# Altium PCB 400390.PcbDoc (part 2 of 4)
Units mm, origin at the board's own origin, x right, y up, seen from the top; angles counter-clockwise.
Board outline 50.8 x 50.4 mm, 4 copper layers (Top Layer, Mid Layer 1, Mid Layer 2, Bottom Layer), stack 1.507 mm thick; 236 components, 197 nets, 1131 pads, 994 vias.
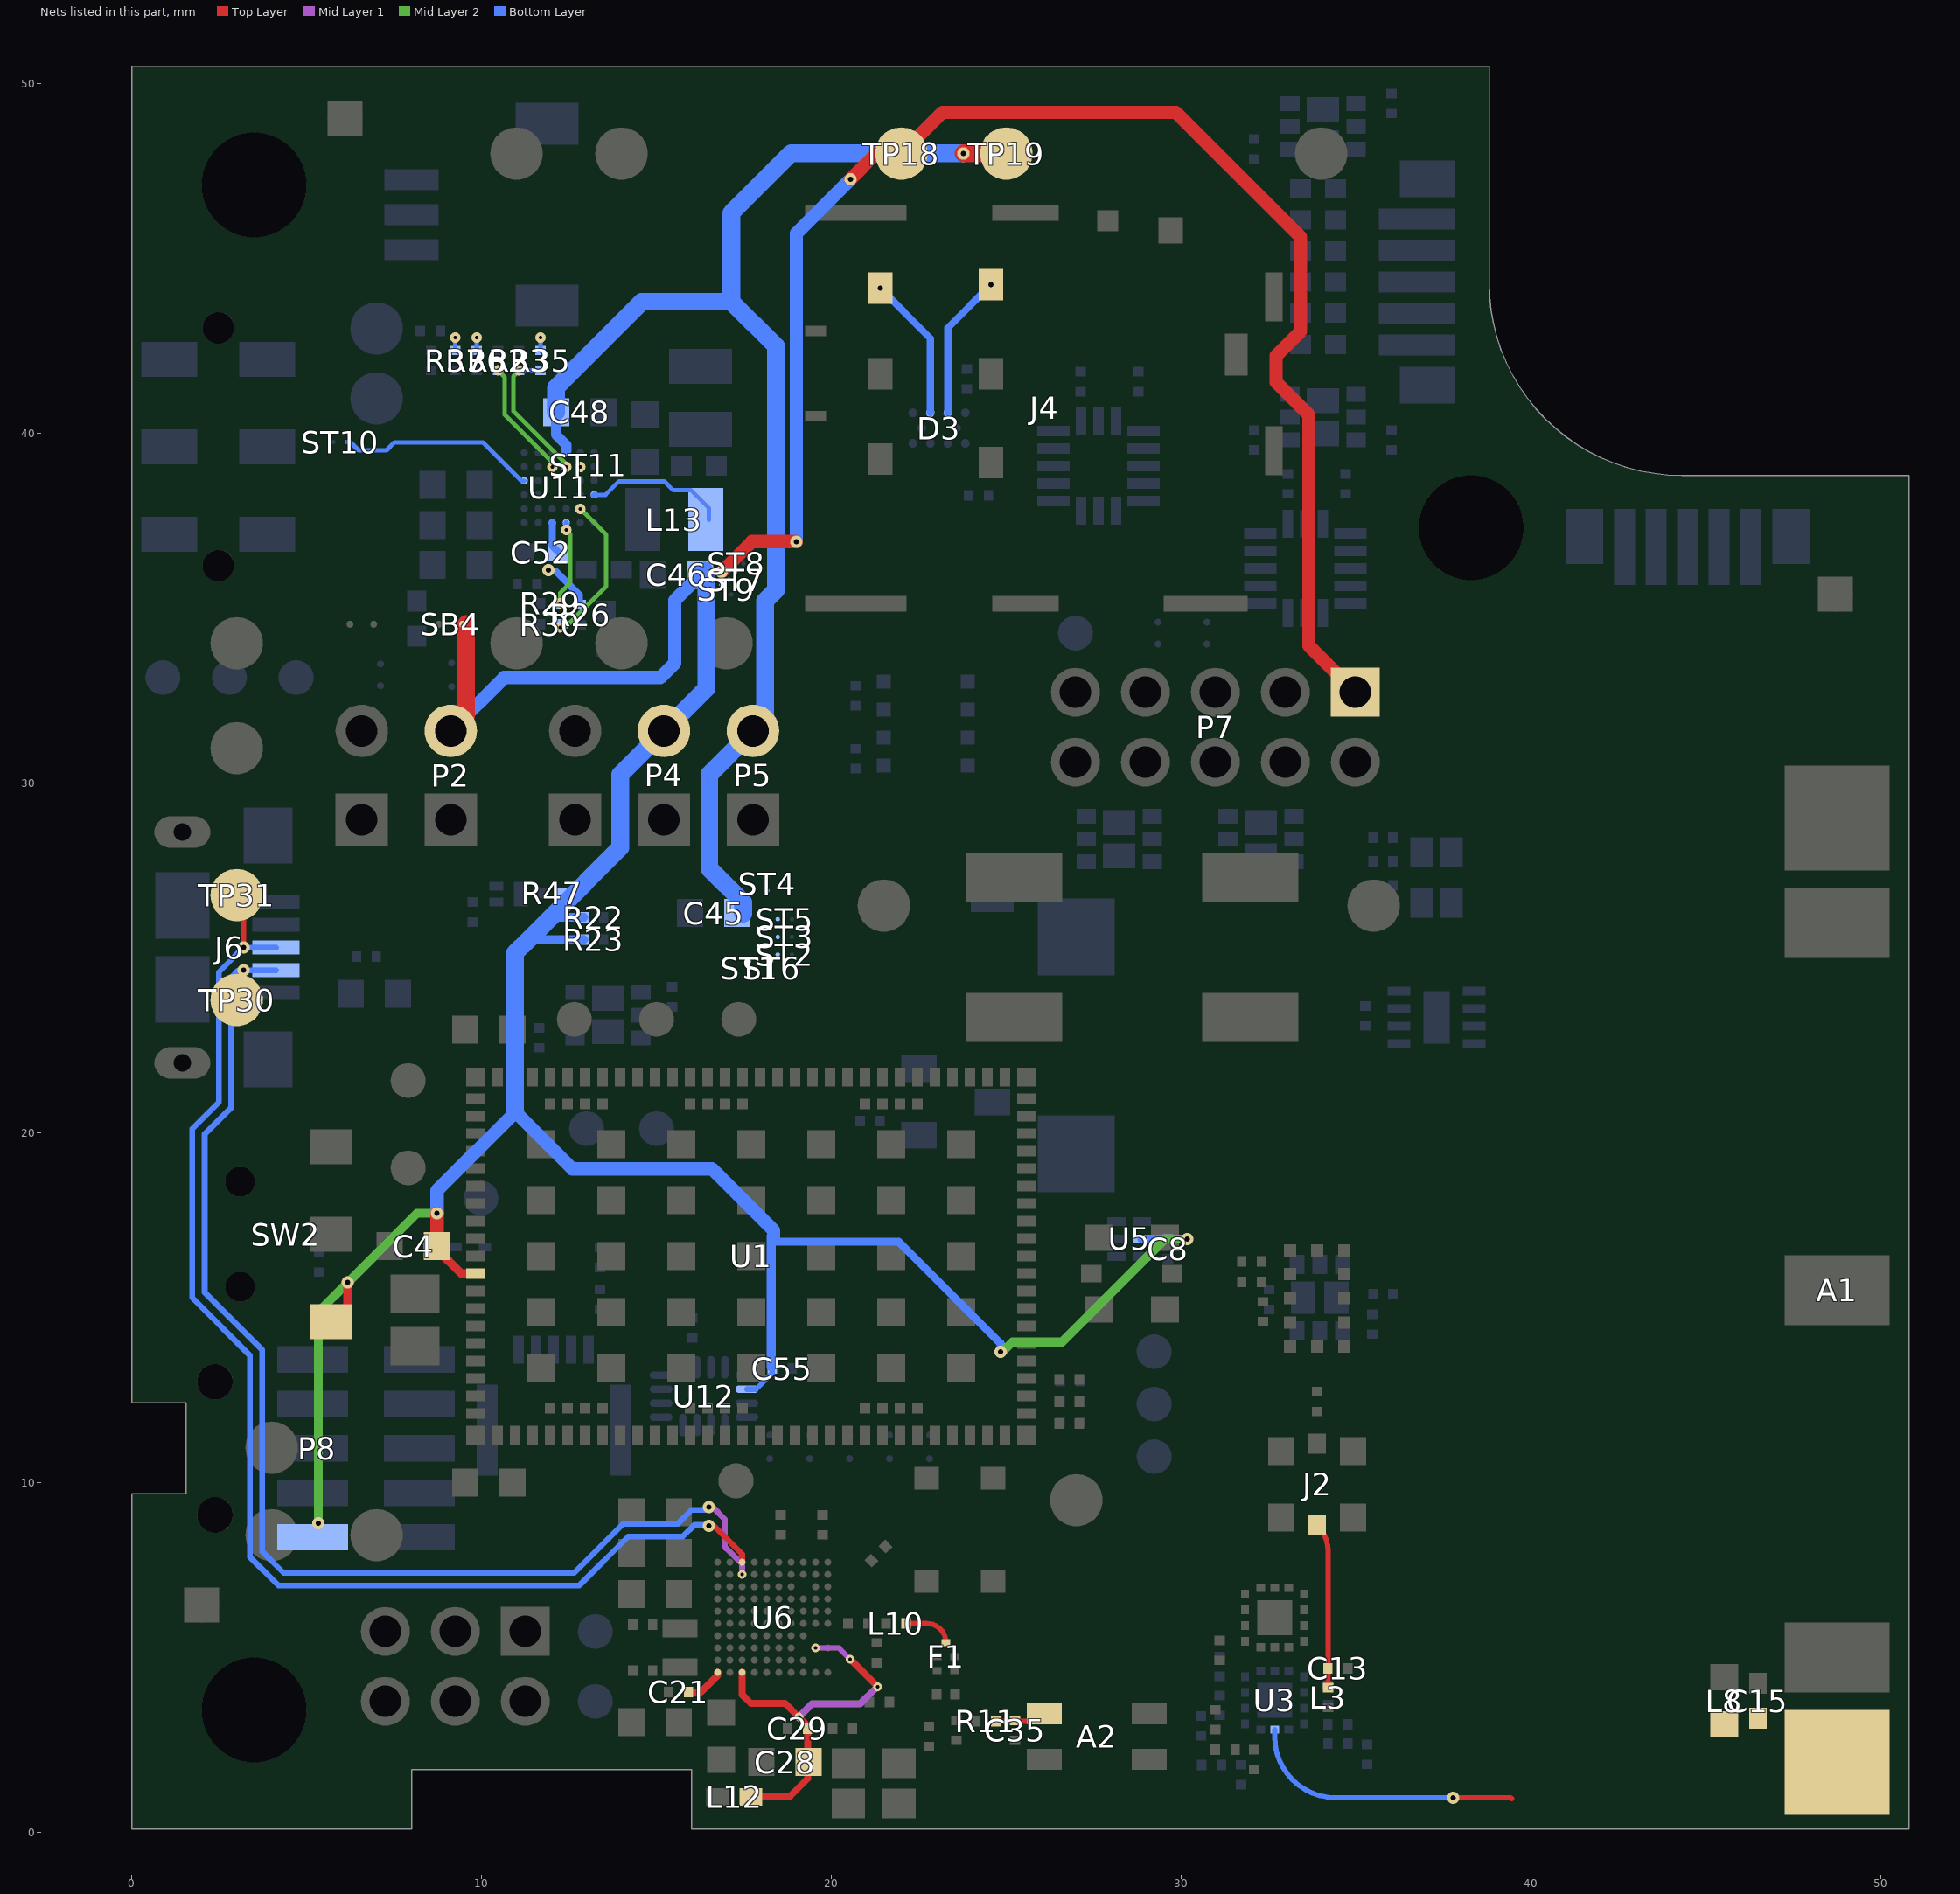
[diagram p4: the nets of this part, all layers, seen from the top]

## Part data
A1: library part FR01-S4-210-D, "Mobile IoT LTE Multi-Band Antenna", Manufacturer="Fractus Antennas", Part number IPS=80000001819
A2: library part "Johanson 2450AT18D0100_STD-R", "2.45 GHz chip antenna", Manufacturer="Johanson Technology", Part number IPS=00000001415, Supplier Part Number 1=2450AT18D0100E
Bz1: library part AST7525MATRQ, "Buzzer Transducer, 3.6V 100mA 2.7kHz 85dB @ 3.6V, SMD", Manufacturer=Mallory, Part number IPS=00000001770, Supplier Part Number 1=458-1100-1-ND
C1 C2 C4 C45 C50: library part C0603-4µ7, "Capacitor, X5R, ±10%", Part number IPS=00000007783
C3: library part C0805-47µ, "Capacitor, X5R, ±20%, 6.3V", Manufacturer="Taiyo Yuden", Manufacturer Part Number=JMK212BJ476MG-T, Part number IPS=N.A., Supplier Part Number 1=587-1779-2-ND
C5: library part C0201-100p, "Capacitor, NP0, ±2%, 25V", Part number IPS=00000007853
C6 C8 C21 C23 C24 C26 C36 C37 C38 C39 C40 C41 C42 C44 C55: library part C0201-100n, "Capacitor, X5R, ±10%", Part number IPS=00000001248
C7: library part C0201-6.8p, "Capacitor, NP0, ±0.25pF, 25V", Part number IPS=00000005766
C9: library part C0201-2.5p-HQ-Murata, "Capacitor, NP0, ±0.05pF, 25V", Manufacturer=Murata, Manufacturer Part Number=GJM0333C1E2R5WB01, Part number IPS=00000001771
C10: library part C0201-5.5p-HQ-Murata, "Capacitor, NP0, ±0.05pF, 25V", Manufacturer=Murata, Manufacturer Part Number=GJM0332C1H5R5WB01, Part number IPS=00000001772
C11: library part C0201-9.2p-HQ-Murata, "Capacitor, NP0, ±0.05pF, 25V", Manufacturer=Murata, Manufacturer Part Number=GJM0332C1E9R2WB01, Part number IPS=N.A.
C12: library part C0201-1.5p-HQ-Murata, "Capacitor, NP0, ±0.05pF, 25V", Manufacturer=Murata, Manufacturer Part Number=GJM0334C1E1R5WB01, Part number IPS=00000001774
C13: library part C0201-3.9p-HQ-Murata, "Capacitor, NP0, ±0.05pF, 25V", Manufacturer=Murata, Manufacturer Part Number=GJM0333C1E3R9WB01, Part number IPS=N.A.
C14: library part C0201-3.1p-HQ-Murata, "Capacitor, NP0, ±0.05pF, 25V", Manufacturer=Murata, Manufacturer Part Number=GJM0335C1E3R1WB01, Part number IPS=00000001776
C15: library part C0402-0.3p-HQ-Murata, "Capacitor, NP0, ±0.05pF, 50V", Manufacturer=Murata, Manufacturer Part Number=GJM1555C1HR30WB01D, Part number IPS=00000001777, Supplier Part Number 1=490-11248-1-ND
C16 C17: library part C0201-2n2, "Capacitor, X7R, ±10%, 10V", Part number IPS=00000001778
C18 C19 C30 C31: library part C0201-12p, "Capacitor, NP0, ±2%", Part number IPS=00000007848
C20: library part C0201-1.0p, "Capacitor, NP0, ±0.05pF, 50V", Part number IPS=00000001247
C22 C32: library part C0603-4µ7-6.3V-X7R, "Capacitor, X7R, ±10%, 6.3V", Manufacturer=Samsung, Manufacturer Part Number=CL10B475KQ8NQNC, Part number IPS=00000002541, Supplier Part Number 1=1276-2087-1-ND
C25: library part C0201-820p, "Capacitor, X7R, ±10%", Part number IPS=00000001249
C27 C28 C49: library part C0603-1µ0, "Capacitor, X7R, ±10%", Part number IPS=00000000616
C29: library part C0201-47n, "Capacitor, X5R, ±10%", Part number IPS=00000001250
C33: library part C0603-4µ7-10V-X7S, "Capacitor, X7S, ±10%, 10V", Part number IPS=00000001779, Supplier Part Number 1=445-14258-1-ND
C35: library part C0201-0.8p, "Capacitor, NP0, ±0.05pF, 50V", Manufacturer=Murata, Manufacturer Part Number=GJM0335C1HR80WB01, Part number IPS=N.A.
C43 C51: library part C0603-10µ, "Capacitor, X5R, ±20%", Part number IPS=00000007785
C46 C48: library part C0603-22µ-6.3V, "CAP CER 22UF 6.3V 20% X5R 0603", Manufacturer=Samsung, Manufacturer Part Number=CL10A226MQ8NRNC, Part number IPS=00000007787, Supplier Part Number 1=1276-1193-1-ND
C47 C52: library part C0402-1µ0, "Capacitor, X5R, ±5%", Part number IPS=00000007786, Supplier Part Number 1=1276-1444-1-ND
C53: library part C0603-2µ2-10V, "Capacitor, X7R, ±10%, 10V", Manufacturer=Samsung, Manufacturer Part Number=CL10B225KP8NNNC, Part number IPS=00000001781, Supplier Part Number 1=1276-1134-1-ND
C54: library part C0201-10n, "Capacitor, X7R, ±10%", Part number IPS=00000003480
C56 C57: library part C0201-560p, "Capacitor, NP0, ±5%, 25V", Part number IPS=N.A.
CR1: "TVS DIODE 4V 0201", Manufacturer=Murata, Part number IPS=00000001782, Supplier Part Number 1=490-14310-1-ND
D1: "20V schottky barrier diode, Vf 350 mV @ 100 mA, Ir 2.0 µA @ 10 V, If 500 mA", Manufacturer="ON Semiconductor", Part number IPS=00000009952, Supplier Part Number 1=NSR0620P2T5GOSCT-ND
D2: "1N4148, Small Signal Fast Switching Diode", Manufacturer=Vishay, Manufacturer Part Number=1N4148W-E3-08, Part number IPS=00000001783, Supplier Part Number 1=237-7282
D3: "EMI Network Filter Arrays SIM CARD EMI FILTER WITH ESD PROTECTION", Manufacturer="ON Semiconductor", Manufacturer Part Number=CM1402-03CP, Part number IPS=00000009949, Supplier Part Number 1=CM1402-03CPOSTR-ND
F1: "2.4 GHz BPF", Manufacturer=MuRata, Part number IPS=00000001784
Fid1 Fid2 Fid3: library part Fid-Mark-Round-Square, "Fiducial Mark", Part number IPS=N.A.
H1 H2 H3: library part Hole_3MM_NP, "Regular Non-Plated, 3mm hole", Manufacturer="Nordic Semiconductor", Part number IPS=N.A.
J1 J2: "Coaxial Connector with Switch", Manufacturer=Murata, Part number IPS=00000009955, Supplier Part Number 1=490-4981-1-ND
J3: library part SM03B-SRSS-TB, "1.0mm pitch connector side entry SMD", Manufacturer=JST, Manufacturer Part Number=SM03B-SRSS-TB(LF)(SN), Part number IPS=00000001785, Supplier Part Number 1=455-1803-1-ND
J4: "n 8 (6 + 2) Position Card Connector NANO SIM Surface Mount, Right Angle Gold", Manufacturer=JAE, Part number IPS=00000009956, Supplier Part Number 1=670-2799-1-ND
J5: library part FPC_05P-0.5mm-RA-SMD, "0.5mm FPC, 5P,Right Angle SMT,Double Contact,H=1.2mm,White, Tin plated", Manufacturer=W-CON, Manufacturer Part Number=5141-05RZDNWR01, Part number IPS=00000007792
J6: library part USB-Micro-B-RA-SMD-PiP, "MicroUSB-B-SMT", Manufacturer="Allen Creations Corp.", Manufacturer Part Number=AJU55-BS2111-L, Part number IPS=00000007790
L1: library part L0201-3n3-Wirewound-Murata, "Inductor, 520mA, ±0.2nH, 110mOhm, Q=47", Manufacturer=Murata, Manufacturer Part Number=LQW03AW3N3C00, Part number IPS=00000001786, Supplier Part Number 1=490-13831-1-ND
L2: library part L0201-5n6, "Inductor, 350mA, ±3%", Manufacturer=Murata, Manufacturer Part Number=LQP03TN5N6H02D, Part number IPS=00000001416
L3: library part L0201-2n9-Wirewound-Murata, "Inductor, 540mA, ±0.2nH, 100mOhm, Q=41", Manufacturer=Murata, Manufacturer Part Number=LQW03AW2N9C00, Part number IPS=00000001787, Supplier Part Number 1=490-13827-1-ND
L4: library part L0201-N.C., "Not mounted", Part number IPS=N.A.
L5: library part L0201-6n2-Wirewound-Murata, "Inductor, 360mA, ±5%, 220mOhm, Q=39", Manufacturer=Murata, Manufacturer Part Number=LQW03AW6N2J00, Part number IPS=N.A., Supplier Part Number 1=490-13840-1-ND
L6: library part L0201-5n1-Wirewound-Murata, "Inductor, 480mA, ±5%, 140mOhm, Q=45", Manufacturer=Murata, Manufacturer Part Number=LQW03AW5N1J00, Part number IPS=00000001789, Supplier Part Number 1=490-13839-1-ND
L7: library part L0201-4n7-Wirewound-Murata, "Inductor, 620mA, ±5%, 90mOhm, Q=45", Manufacturer=Murata, Manufacturer Part Number=LQW03AW4N7J00, Part number IPS=00000001790, Supplier Part Number 1=490-13838-1-ND
L8: library part L0603-15n-HQ-Murata, "Inductor, 1400mA, ±2%, 75mOhm", Manufacturer=Murata, Manufacturer Part Number=LQW18AN15NG80D, Part number IPS=00000001791, Supplier Part Number 1=490-18132-1-ND
L9: library part L0201-3n9, "Inductor, 400mA, ±0.1nH", Manufacturer=Murata, Manufacturer Part Number=LQP03TN3N9B02D, Part number IPS=00000001253
L10: library part L0201-4n7, "Inductor, 350mA, ±3%", Manufacturer=Murata, Manufacturer Part Number=LQP03TN4N7H02D, Part number IPS=00000001792
L11: library part L0603-10µ, "Inductor, 80mA, ±10%", Manufacturer="Taiyo Yuden", Manufacturer Part Number=LBMF1608T100K, Part number IPS=00000007794, Supplier Part Number 1=587-1714-1-ND
L12: library part L0402-15n, "Inductor, 320mA, ±5%", Manufacturer="Taiyo Yuden", Manufacturer Part Number=HK100515NJ-T, Part number IPS=00000001262, Supplier Part Number 1=587-1521-1-ND
L13 L14: library part L0806-2µ2-1.2A-110mOhm, "Shielded Multilayer Inductor, 1.2A, ±20%, 110mOhm, Q=10 @ 1MHz", Manufacturer="Wurth Electronics", Manufacturer Part Number=74479776222A, Part number IPS=80000001820, Supplier Part Number 1=732-2954-1-ND
L15: library part L0201-2n7-HQ-Murata, "Inductor, 600mA, ±0.1nH, 120mOhm", Manufacturer=Murata, Manufacturer Part Number=LQP03HQ2N7B02, Part number IPS=N.A., Supplier Part Number 1=490-13909-1-ND
LD1: library part LTST-C19HE1WT, "RGB LED 1.60 mm x 1.60 mm SMD", Manufacturer="Lite-On Inc", Part number IPS=00000007798, Supplier Part Number 1=160-2162-1-ND
LD2 LD3: library part MSL0104RGBU1, "High brightness, side view RGB LED", Manufacturer=ROHM, Part number IPS=00000007799, Supplier Part Number 1=MSL0104RGBU1CT-ND
P1 P2 P3 P4 P5: library part "Pin List 1x2, N.C.", "Pin List 1x2, 2.54mm (100mil)", Part number IPS=N.A.
P6: library part "Pin Header 2x3 TH, 2.00mm, N.C.", "Pin Header 2x3, TH, 2.00mm", Part number IPS=N.A.
P7: library part "Pin Header 2x5 TH, 2.00mm, N.C.", "Pin Header 2x5, TH, 2.00mm", Part number IPS=N.A.
P8: library part "Pin Header 2x5 SMD, 1.27mm, Angled", "Pin Header 2x5, 1.27mm (50mil)", Manufacturer=Samtec, Manufacturer Part Number=FTSH-105-01-L-DH-A-C-TR, Part number IPS=00000007800
Q1: "Dual N & P Ch MOFET, 11.6A/9A, 90mOhm max, 6.25W", Manufacturer="Taiwan Semiconductor", Part number IPS=00000001702, Supplier Part Number 1=TSM2537CQRFGCT-ND
Q2 Q3 Q4 Q6 Q7: "Dual N Ch MOFET, 5.8A, 55mOhm max, 620mW", Manufacturer="Taiwan Semiconductor", Part number IPS=00000001703, Supplier Part Number 1=TSM250N02DCQRFGCT-ND
Q5: "BC847C, NPN Silicon transistor", Manufacturer=NXP, Part number IPS=00000001793, Supplier Part Number 1=108-1235
Q8: "N-Channel MOSFET, 20V, 1A, 470mOhm, 400mW", Manufacturer="Rohm Semiconductor", Part number IPS=N.A., Supplier Part Number 1=RV2C010UNT2LCT-ND
R1 R2 R3 R21 R47: library part R0201-1k0, "Resistor, ±1%, 0.05W", Part number IPS=00000005786
R4 R5 R6 R8 R30 R32 R41 R42 R43 R44 R45 R46: library part R0201-1M0, "Resistor, ±1%, 0.05W", Part number IPS=00000001418
R7: library part R0201-3k0, "Resistor, ±1%, 0.05W", Part number IPS=00000001688
R9 R10 R11 R38: library part R0201-0R, "Resistor, ±5%, 0.05W", Part number IPS=00000003245
R12: library part R0201-100, "Resistor, ±1%, 0.05W", Part number IPS=00000001794
R13 R14: library part R0201-39R, "Resistor, ±1%, 0.05W", Part number IPS=00000001704
R15 R18: library part R0402-169, "Resistor, ±1%, 0.063W", Part number IPS=00000007805, Supplier Part Number 1=541-169LCT-ND
R16 R19: library part R0402-7R15, "Resistor, ±1%, 0.063W", Part number IPS=00000007806, Supplier Part Number 1=541-7.15LLCT-ND
R17 R20: library part R0402-11R, "Resistor, ±1%, 0.063W", Part number IPS=00000007807, Supplier Part Number 1=214-0577
R22 R23: library part R0201-4k7, "Resistor, ±1%, 0.05W", Part number IPS=00000001706
R24: library part R0402-0R1, "Resistor, ±1%, 0.063W", Part number IPS=00000001795, Supplier Part Number 1=311-.10PDKR-ND
R25 R31: library part R0402-2R2, "Resistor, ±1%, 0.063W", Part number IPS=00000001796
R26 R29 R33: library part R0201-N.C., "Not mounted", Part number IPS=N.A.
R27 R28 R34 R35 R36 R37: library part R0201-10k, "Resistor, ±1%, 0.05W", Part number IPS=00000001255
R39 R40: library part R0201-100k, "Resistor, ±1%, 0.05W", Part number IPS=00000001419
R48: library part R0201-10M, "Resistor, ±1%, 0.05W", Part number IPS=00000001426
SB1 SB3 SB4 SB7 SB8 SB9 SB10 SB11: library part "Solderbridge Shorted", "Shorted Solderbridge", Part number IPS=N.A.
SB2 SB5 SB6: Part number IPS=N.A.
ST1 ST2 ST3 ST4 ST5 ST6 ST7 ST8 ST9 ST10 ST11: library part "2 pin starpoint", "Starpoint", Part number IPS=N.A.
SW1: library part Switch-Slide-RA-J-Lead-DPDT-8.5x3.5mm_Copal, "SMD slide Switch (ON-ON)", Manufacturer="Copal Electronics Inc", Manufacturer Part Number=CL-SB-22A-11T, Part number IPS=00000007811, Supplier Part Number 1=563-1340-1-ND
SW2: "Miniature slide switch, SPDT, Right-Angle, ON-ON, 12V, 100mA", Manufacturer=C&K, Part number IPS=N.A., Supplier Part Number 1=401-2012-1-ND
SW3: library part Switch-PB-6.2x6.3mm-SMD, "Tactile Switch, SPNO, SMD, 160gf, 6.2x6.3x2.5mm", Manufacturer=Dailywell, Manufacturer Part Number=TS604VM1-025BR-R, Part number IPS=00000007812
SW4: library part "KMT021 NGJ LHS", "Nano-Miniature Top Actuated Tact Switch with extended life 3.0x2.6mm", Manufacturer="C & K", Part number IPS=N.A., Supplier Part Number 1=CKN10289CT-ND
TP1 TP2 TP3 TP4 TP5 TP6 TP7 TP8 TP22 TP23 TP24 TP25 TP26 TP34 TP35 TP36 TP37 TP38: library part TP_SMD_Ø1.0MM, "1.0mm circular SMD testpad", Manufacturer="Nordic Semiconductor", Part number IPS=N.A.
TP9 TP10 TP11 TP12 TP13 TP14 TP15 TP16 TP17 TP18 TP19 TP20 TP21 TP27 TP28 TP29 TP30 TP31 TP32 TP33: library part TP_SMD_Ø1.5MM, "1.0mm circular SMD testpad", Manufacturer="Nordic Semiconductor", Part number IPS=N.A.
U1: "Low power System-in-Package with integrated LTE-M/NB-IoT modem and GPS", Manufacturer="Nordic Semiconductor", Part number IPS=N.A.
U2 U3: "SP8T Switch For 3G/4G Applications", Manufacturer=Qorvo, Part number IPS=80000001821
U4: "GPS, GLONASS, and BeiDou Low Noise Amplifier With Integrated Output SAW Filter, 1.55 to 1.61 GHz, 13.5 dB", Manufacturer=Qorvo, Part number IPS=80000001649
U5: "Single 3-input AND gate", Manufacturer="ON Semiconductor", Part number IPS=00000001709, Supplier Part Number 1=NC7SV11L6XCT-ND
U6: library part nRF52840-CKAAD0, "Multi-protocol Bluetooth Low Energy, IEEE 802.15.4, ANT and 2.4GHz proprietary system-on-chip", Manufacturer="Nordic Semiconductor", Part number IPS=80000001822
U7: "Micropower, 3-Axis, ±200g digital output acelerometer", Manufacturer="Analog Devices", Part number IPS=00000001798, Supplier Part Number 1=ADXL372BCCZ-RL7CT-ND
U8: "Micropower, 3-Axis, ±2 g/±4 g/±8 g Digital Output MEMS Accelerometer", Manufacturer="Analog Devices", Part number IPS=00000001799, Supplier Part Number 1=ADXL362BCCZ-RL7CT-ND
U9: "Low power gas, pressure, temperature & humidity sensor", Manufacturer=Bosch, Part number IPS=00000001800, Supplier Part Number 1=828-1077-1-ND
U10: "Digital 16bit Serial Output Type Color Sensor IC", Manufacturer="Rohm Semiconductor", Part number IPS=00000001801, Supplier Part Number 1=BH1749NUC-E2CT-ND
U11: "Advanced Battery Management PMIC With Ultralow Iq Buck and Buck-Boost", Manufacturer="Analog Devices", Part number IPS=80000001823
U12: "Data / Audio Low-Voltage Dual DPDT Analog Switch", Manufacturer="Fairchild Semiconductor", Part number IPS=00000009986, Supplier Part Number 1=FSA2466UMXCT-ND
X1: library part XTAL_SMD2016_32MHz_8pF_Golledge, "XTAL SMD 2016, 32MHz, Cl=8pF, Tol: ±10ppm, Stab: ±15ppm", Manufacturer=Golledge, Manufacturer Part Number=MP06003, Part number IPS=00000001431
X2: library part XTAL_SMD1610_32.768kHz_9pF_Seiko, "XTAL SMD 1610, 32.768kHz, 9pF, ±20ppm", Manufacturer=Seiko, Manufacturer Part Number=SC16S-9.0PF20PPM, Part number IPS=00000001802

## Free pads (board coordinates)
  round 0.25 on Mech16: 1(15.829,3.556) 1(17.097,4.926) 1(17.097,5.276) 1(17.097,5.626) 1(17.097,5.976) 1(17.097,6.676) 1(17.097,7.376) 1(17.447,7.026) 1(17.447,4.926) 1(17.447,7.376) 1(17.797,4.926) 1(17.797,7.376) 1(18.147,7.376) 1(18.497,7.376) 1(18.847,4.576) 1(18.847,7.376) 1(19.197,4.926) 1(19.197,7.376) 1(19.547,5.272) 1(19.547,5.976) 1(19.547,6.326) 1(19.547,6.676) 1(19.547,7.026) 1(19.547,7.376) ""(21.006,7.671) ""(21.742,8.255)
  round 0.35 on Mech16: 1(17.655,6.023) 1(18.491,5.969) 2(19.544,40.488) 2(19.544,42.928) 2(21.394,39.268) 2(21.394,41.708) 2(21.394,44.148) 2(24.564,39.168) 2(24.564,44.248) 2(31.569,42.258) 2(38.426,23.05) 2(38.426,23.55) 2(38.426,24.05) ""(9.509,37.379) ""(9.509,37.379) ""(9.836,11.357) ""(9.836,13.477) ""(9.836,14.977) ""(9.836,17.477) ""(9.836,19.477) ""(9.836,21.597) ""(11.706,14.877) ""(11.706,16.477) ""(11.706,18.077) ""(11.706,19.677) ""(11.706,13.277) ""(11.916,36.084) ""(12.456,21.597) ""(12.956,11.357) ""(13.689,40.375) ""(13.689,40.832) ""(13.706,14.877) ""(13.706,16.477) ""(13.706,18.077) ""(13.706,19.677) ""(13.706,13.277) ""(14.376,40.513) ""(14.456,21.597) ""(14.553,36.182) ""(14.554,35.75) ""(14.653,12.271) ""(14.884,40.513) ""(14.956,11.357) ""(15.037,35.75) ""(15.037,36.182) ""(15.706,19.677) ""(15.706,13.277) ""(15.706,14.877) ""(15.706,16.477) ""(15.706,18.077) ""(16.456,21.597) ""(16.764,39.065) ""(16.956,11.357) ""(17.456,11.357) ""(17.706,18.077) ""(17.706,13.429) ""(17.706,14.877) ""(17.706,16.477) ""(17.706,19.677) ""(17.907,12.268) ""(18.956,21.597) ""(19.706,13.429) ""(19.706,14.877) ""(19.706,16.477) ""(19.706,18.077) ""(19.706,19.677) ""(20.456,21.597) ""(20.956,21.597) ""(21.456,21.597) ""(21.706,14.877) ""(21.706,13.379) ""(21.706,16.477) ""(21.706,18.077) ""(21.706,19.677) ""(21.956,21.597) ""(22.456,21.597) ""(22.723,10.129) ""(22.956,11.357) ""(22.956,21.597) ""(23.456,21.597) ""(23.706,13.277) ""(23.706,14.877) ""(23.706,16.477) ""(23.706,18.077) ""(23.706,19.677) ""(23.956,21.597) ""(24.456,11.357) ""(24.456,21.597) ""(25.576,11.357) ""(25.576,13.477) ""(25.576,15.477) ""(25.576,16.477) ""(25.576,16.977) ""(25.576,17.977) ""(25.576,18.477) ""(25.576,21.597) ""(31.096,4.462) ""(31.101,5.469) ""(31.608,3.556) ""(32.112,2.664) ""(33.734,6.819) ""(33.734,3.556)
  round 0.3 on Mech16: ""(9.249,41.799) ""(9.858,41.799) ""(10.468,41.799) ""(11.078,41.799) ""(11.621,37.846) ""(11.621,38.246) ""(11.621,38.646) ""(11.621,39.046) ""(12.021,37.846) ""(12.021,39.046) ""(12.252,34.458) ""(12.252,35.144) ""(12.421,37.243) ""(12.421,37.846) ""(12.421,39.046) ""(12.821,37.846) ""(12.821,38.246) ""(12.821,38.646) ""(12.821,39.046) ""(12.957,34.529)

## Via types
v1: diameter 0.35, hole 0.15, Top Layer to Bottom Layer, tented both sides, 565 vias
v2: diameter 0.35, hole 0.15, Top Layer to Mid Layer 1, tented both sides, 201 vias
v3: diameter 0.35, hole 0.15, Mid Layer 2 to Bottom Layer, tented both sides, 153 vias
v4: diameter 0.25, hole 0.1, Top Layer to Mid Layer 1, tented both sides, 35 vias
v5: diameter 0.3, hole 0.1, Mid Layer 2 to Bottom Layer, tented both sides, 26 vias
v6: diameter 0.25, hole 0.1, Mid Layer 2 to Bottom Layer, tented both sides, 5 vias
v7: diameter 0.35, hole 0.15, Top Layer to Mid Layer 1, 4 vias
v8: diameter 0.3, hole 0.1, Top Layer to Mid Layer 1, tented both sides, 3 vias
v9: diameter 0.61, hole 0.305, Top Layer to Bottom Layer, tented both sides, 2 vias

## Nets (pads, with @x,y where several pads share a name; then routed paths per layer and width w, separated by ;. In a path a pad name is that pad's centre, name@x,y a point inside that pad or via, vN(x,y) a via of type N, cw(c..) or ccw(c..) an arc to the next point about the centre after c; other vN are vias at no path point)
1V8: C4.1 C8.2 C46.2 C55.1 L13.2 P2.2 P4.2 P7.1 P8.1 R22.1 R23.1 R47.1 SB4.2 ST7.1 ST8.1 ST9.1 SW2.3 TP18.1 U1.12 U5.5 U11.D1 U12.14 | length 128.4
  Top Layer w0.254: SW2.3@5.7,14.6 6.175,15.075 v1(6.175,15.725) ; C4.1@8.727,16.764 8.727,16.673 9.423,15.977 U1.12@9.836,15.977
  Top Layer w0.381: C4.1@8.727,16.764 v1(8.727,17.704) ; v1(16.866,36.043) 17.729,36.906 v1(18.999,36.906) ; v1(20.549,47.269) 21.279,48 TP18.1@22,48 23.174,49.174 29.845,49.174 33.409,45.61 33.409,42.92 32.707,42.218 32.707,41.461 33.645,40.523 33.645,33.93 P7.1@34.975,32.6
  Top Layer w0.508: P2.2@9.119,31.496 9.56,31.937 9.56,34.544
  Mid Layer 2 w0.254: v1(5.334,8.839) 5.334,14.884 v1(6.175,15.725) 8.154,17.704 v1(8.727,17.704) ; v3(24.841,13.741) 24.892,13.741 25.171,14.021 26.594,14.021 29.54,16.967 v3(30.175,16.967)
  Bottom Layer w0.125: U11.D1@13.221,38.246 13.545,38.246 13.929,38.631 15.224,38.631 15.482,38.373 15.991,38.373 16.494,37.87 L13.2@16.494,37.523
  Bottom Layer w0.152: U11.D1@13.199,38.23 U11.D1@13.22,38.247 ; U12.14@17.583,12.671 17.847,12.671 18.308,13.132 C55.1@18.308,13.259
  Bottom Layer w0.229: 18.35,16.891 21.92,16.891 24.841,13.97 v3(24.841,13.741)
  Bottom Layer w0.254: 11.341,25.527 R23.1@12.923,25.527 ; 11.976,26.162 R22.1@12.923,26.162 ; C55.1@18.279,13.301 18.279,17.056 ; U5.5@28.876,16.967 v3(30.175,16.967)
  Bottom Layer w0.381: v1(8.727,17.704) 8.727,18.353 10.969,20.595 ; P2.2@9.119,31.496 10.643,33.02 15.113,33.02 15.519,33.426 15.519,35.224 C46.2@16.251,35.956 ; 11.031,20.533 12.591,18.974 16.586,18.974 18.349,17.211 18.349,16.966 ; v1(18.999,36.906) 18.999,45.72 v1(20.549,47.269)
  Bottom Layer w0.508: 10.969,20.595 10.956,20.608 10.956,25.142 11.341,25.527 11.976,26.162 13.97,28.156 13.97,30.251 P4.2@15.215,31.496 16.429,32.711 C46.2@16.429,35.835 ; C46.2@16.256,36.065 16.256,35.95 C46.2@16.374,36.068
3V3: C45.2 C48.2 P5.2 ST1.1 ST2.1 ST3.1 ST4.1 ST5.1 ST6.1 TP19.1 U11.A3 | length 38.1
  Top Layer w0.508: v1(23.774,48.006) 24.994,48.006 TP19.1@25,48
  Bottom Layer w0.152: U11.A3@12.421,39.463 12.428,39.45 U11.A3@12.43,39.446
  Bottom Layer w0.3: C48.2@12.13,40.427 12.13,39.959 12.421,39.668 U11.A3@12.421,39.5
  Bottom Layer w0.508: C48.2@12.13,40.605 12.13,41.314 14.58,43.764 17.145,43.764 ; C45.2@17.475,26.264 17.475,26.594 16.51,27.559 16.51,30.251 P5.2@17.755,31.496 18.103,31.844 18.103,35.206 18.415,35.518 18.415,42.494 17.145,43.764 ; v1(23.774,48.006) 18.847,48.006 17.145,46.304 17.145,43.764
AGND: C52.1 R26.2 R35.1 R36.2 R37.2 ST11.1 U11.B2 U11.F4 | length 3.2
  Bottom Layer w0.125: R37.2@9.249,42.369 v5(9.249,42.739) ; R36.2@9.858,42.369 v5(9.858,42.739) ; R35.1@11.687,42.369 v5(11.687,42.739)
  Bottom Layer w0.203: U11.F4@12.021,37.446 12.021,36.781 C52.1@12.201,36.601 ; 12.144,36.033 12.799,35.378 R26.2@12.799,35.144
  other v3: 11.916,36.084
  other v5: 12.821,39.046
ANT_GPS: C13.2 J2.3 L3.1 | length 4.7
  Top Layer w0.146: J2.3@33.888,8.794 cw(c33.146,8.052) 34.195,8.052 34.195,7.69 L3.1@34.195,4.143
ANT_LTE: A1.1 C15.1 L8.1 U3.13 | length 8
  Top Layer w0.146: v1(37.77,0.991) 39.385,0.991 cw(c39.385,0.904) 39.446,0.965
  Bottom Layer w0.146: U3.13@32.671,2.936 32.671,2.736 ccw(c34.417,2.736) 34.417,0.991 v1(37.77,0.991)
BLE_ANT: A2.1 C35.1 R11.2 | length 1.2
  Top Layer w0.146: R11.2@24.697,3.175 A2.1@25.873,3.175
BLE_RF: F1.1 L10.2 | length 1.5
  Top Layer w0.146: L10.2@22.132,5.976 22.723,5.976 cw(c22.723,5.425) F1.1@23.275,5.425
BSNS: ST10.1 U11.C6 | length 5.7
  Bottom Layer w0.125: ST10.1@6.147,39.751 6.248,39.751 6.484,39.515 7.283,39.515 7.506,39.739 10.04,39.739 11.133,38.646 U11.C6@11.221,38.646
CLK_1: D3.C2 J4.C3 | length 4.2
  Bottom Layer w0.203: v1(21.394,44.148) 22.828,42.715 D3.C2@22.828,40.592
D_N: J6.2 TP30.1 U6.J8 | length 35.9
  Top Layer w0.165: TP30.1@3,23.8 3.2,24 v1(3.2,24.65)
  Mid Layer 1 w0.165: v1(16.493,9.301) 16.607,9.301 16.951,8.957 16.951,8.167 17.092,8.026 17.447,7.671 v4(17.447,7.376)
  Bottom Layer w0.165: J6.2@4.125,24.65 v1(3.2,24.65) 3.05,24.65 2.847,24.447 2.847,20.73 2.085,19.968 2.085,15.439 3.734,13.791 3.734,8.025 4.339,7.419 12.646,7.419 14.043,8.816 15.6,8.816 16.004,9.22 16.413,9.22 v1(16.493,9.301)
D_P: J6.3 TP31.1 U6.K8 | length 36.7
  Top Layer w0.165: TP31.1@3,26.55 3.194,26.356 v1(3.194,25.3) ; v1(16.493,8.767) 16.639,8.767 17.447,7.959 U6.K8@17.447,7.726
  Bottom Layer w0.165: J6.3@4.125,25.3 v1(3.194,25.3) 2.489,24.596 2.489,20.879 1.727,20.117 1.727,15.291 3.376,13.642 3.376,7.877 4.191,7.061 12.795,7.061 14.192,8.458 15.748,8.458 16.082,8.793 v1@16.493,8.793
DATA_1: D3.C3 J4.C7 | length 4.2
  Bottom Layer w0.203: D3.C3@23.328,40.592 23.328,43.012 v1(24.564,44.248)
DEC1: C21.1 U6.A10 | length 1.1
  Top Layer w0.2: C21.1@15.915,4.017 16.273,4.017 16.747,4.492 U6.A10@16.747,4.576
DEC4_6: C28.2 C29.1 L12.1 U6.A8 U6.C2 | length 11
  Top Layer w0.2: U6.A8@17.447,4.576 17.447,3.94 17.693,3.694 18.671,3.694 19.067,3.298 19.069,3.298 19.283,3.083 19.283,3.011 19.318,2.976 19.318,1.534 18.805,1.02 L12.1@17.699,1.02 ; v4(20.532,4.957) v4(21.319,4.17)
  Mid Layer 1 w0.15: v4(19.547,5.272) 20.217,5.272 v4(20.532,4.957)
  Mid Layer 1 w0.2: v4(19.074,3.306) 19.445,3.677 20.826,3.677 v4@21.269,4.119
EN1: R30.2 U11.E2 | length 4.3
  Mid Layer 2 w0.125: v5(12.252,34.458) 12.397,34.458 13.564,35.625 13.564,37.103 v5(12.821,37.846)
EN2: R32.2 U11.B4 | length 3.4
  Mid Layer 2 w0.125: v5(10.468,41.799) 10.66,41.606 10.66,40.53 12.023,39.167 v5@12.023,39.02
  other v5: 12.021,39.046
ENCHG: R29.2 U11.F3 | length 2.5
  Mid Layer 2 w0.125: v5(12.252,35.144) 12.252,35.442 12.533,35.723 12.533,37.131 v5(12.421,37.243)
  Bottom Layer w0.152: v5(12.421,37.243) U11.F3@12.421,37.446
ENSD: R33.1 R35.2 U11.B3 | length 4.1
  Mid Layer 2 w0.125: v5(11.078,41.799) 10.91,41.632 10.91,40.633 12.421,39.123 v5(12.421,39.046)
  Bottom Layer w0.125: v5(11.078,41.799) R35.2@11.687,41.799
